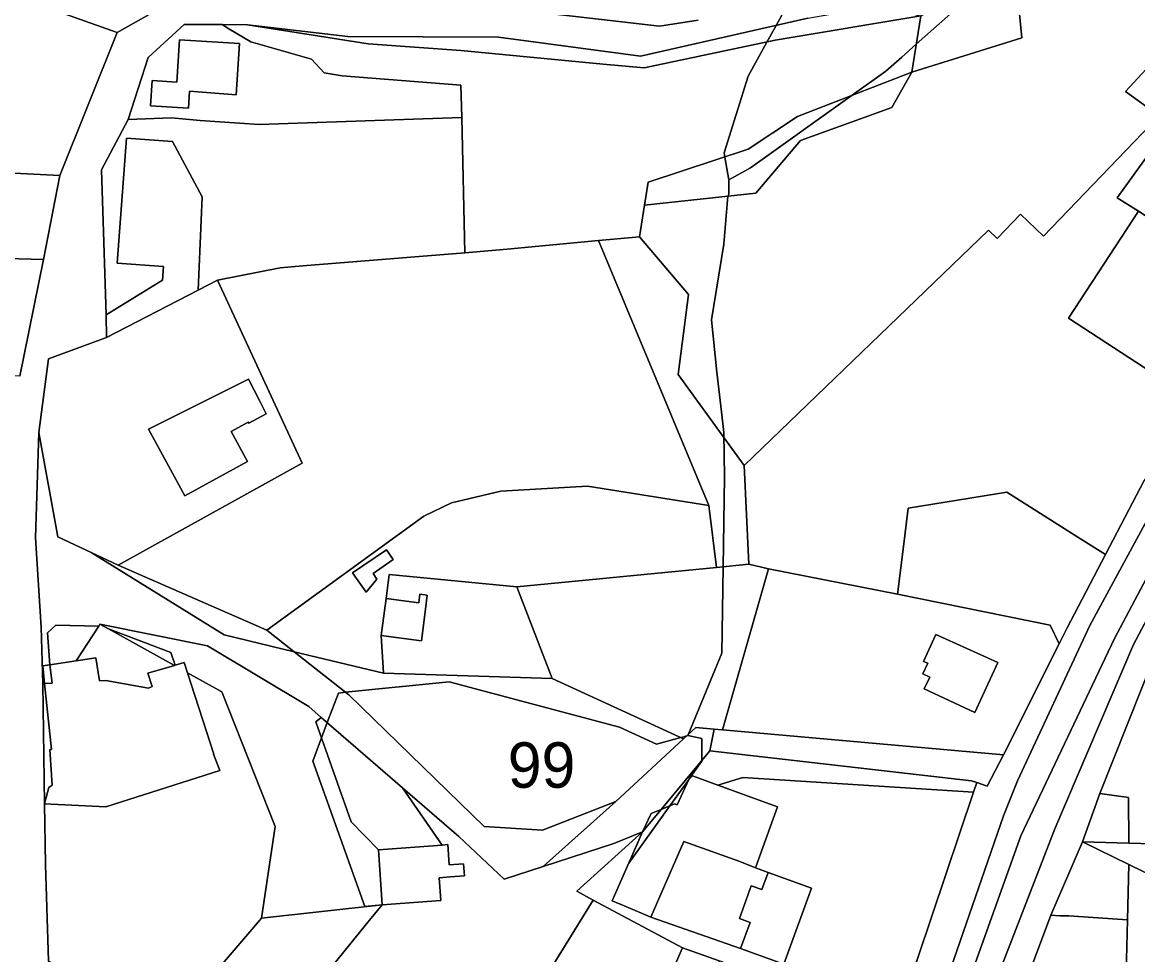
# Model space of a CAD drawing. Extents: x -502026 to -497664, y -1143484 to -1138019.
# Drawn here: x -498249.6 to -498053.3, y -1140095.6 to -1139931.4 of the extents above; entities that cross this region are included whole.
import ezdxf

# ---------------------------------------------------------------- set-up
doc = ezdxf.new("R2010")
doc.units = 0
for name, color, linetype in [('25', 7, 'Continuous'), ('31', 7, 'Continuous'), ('37', 7, 'Continuous'), ('49', 7, 'Continuous'), ('55', 7, 'Continuous'), ('62', 7, 'Continuous'), ('7', 7, 'Continuous')]:
    doc.layers.add(name, color=color, linetype=linetype)

msp = doc.modelspace()

# ---------------------------------------------------------------- linework, layer by layer
at = {"layer": '25'}
for points in [[(-498232.94, -1139933.15), (-498243, -1139958.38), (-498284.72, -1139956.22), (-498294.84, -1139955.69), (-498271.76, -1139932.13), (-498277.06, -1139927.13), (-498281.47, -1139922.96), (-498283.61, -1139920.94), (-498270.97, -1139913.76), (-498253.45, -1139925.83)], [(-498005.22, -1139919.56), (-498013.29, -1139944.08), (-498013.7, -1139945.33), (-498022.56, -1139967.15), (-498037.76, -1139956.26), (-498047.52, -1139949.27), (-498049.52, -1139947.83), (-498055.44, -1139943.59), (-498027.12, -1139912.89)], [(-498093.06, -1139940.14), (-498113.16, -1139947.96), (-498121.83, -1139953.73), (-498139.45, -1139959.55), (-498140.08, -1139963.56), (-498140.96, -1139969.15), (-498148.2, -1139969.82), (-498164.29, -1139971.31), (-498171.75, -1139971.96), (-498172.29, -1139948.12), (-498172.42, -1139942.47), (-498193.31, -1139940.83), (-498196.52, -1139940.26), (-498198.73, -1139937.88), (-498209.39, -1139934.8), (-498213.26, -1139932.52), (-498214.48, -1139931.78), (-498209.97, -1139931.8), (-498188.75, -1139935.17), (-498172.43, -1139936.37), (-498147.36, -1139938.76), (-498140.19, -1139939.42), (-498117.09, -1139934.55), (-498091.45, -1139930.24)], [(-498214.48, -1139931.78), (-498213.26, -1139932.52), (-498209.39, -1139934.8), (-498198.73, -1139937.88), (-498196.52, -1139940.26), (-498193.31, -1139940.83), (-498172.42, -1139942.47), (-498172.29, -1139948.12), (-498207.94, -1139949.35), (-498218.35, -1139948.67), (-498223.36, -1139948.18), (-498230.99, -1139948.51), (-498227.48, -1139937.56), (-498221.15, -1139931.74)], [(-498211.43, -1139935.09), (-498221.96, -1139934.44), (-498222.42, -1139941.91), (-498226.78, -1139941.61), (-498227.07, -1139946.11), (-498220.39, -1139946.52), (-498220.2, -1139943.51), (-498211.98, -1139944.15)], [(-498171.75, -1139971.96), (-498200.23, -1139974.26), (-498204.27, -1139974.59), (-498215.25, -1139976.79), (-498218.65, -1139978.55), (-498217.95, -1139962.1), (-498223.18, -1139952.37), (-498231.27, -1139951.77), (-498232.95, -1139973.77), (-498224.77, -1139974.36), (-498224.96, -1139976.78), (-498234.9, -1139982.88), (-498235.68, -1139957.35), (-498230.99, -1139948.51), (-498223.36, -1139948.18), (-498218.35, -1139948.67), (-498207.94, -1139949.35), (-498172.29, -1139948.12)], [(-498047.52, -1139949.27), (-498056.92, -1139962.31), (-498053.17, -1139964.63), (-498065.44, -1139983.49), (-498043.03, -1139998.07), (-498052.15, -1140012.08), (-498058.96, -1140025.11), (-498063.8, -1140022.04), (-498076.32, -1140014.11), (-498093.67, -1140016.92), (-498094.53, -1140023.68), (-498095.59, -1140032.09), (-498118.27, -1140027.6), (-498121.71, -1140026.79), (-498122.55, -1140009.45), (-498079.55, -1139968), (-498078.04, -1139969.45), (-498073.93, -1139965.16), (-498069.88, -1139969.05), (-498049.52, -1139947.83)], [(-498037.76, -1139956.26), (-498038.47, -1139957.24), (-498039.95, -1139959.31), (-498046.76, -1139968.79), (-498053.17, -1139964.63), (-498056.92, -1139962.31), (-498047.52, -1139949.27)], [(-498243, -1139958.38), (-498245.93, -1139973.13), (-498261.03, -1139972.75), (-498285.83, -1139972.19), (-498285.53, -1139967.92), (-498284.84, -1139957.94), (-498284.72, -1139956.22)], [(-498046.76, -1139968.79), (-498030.37, -1139979.5), (-498043.03, -1139998.07), (-498065.44, -1139983.49), (-498053.17, -1139964.63)], [(-498122.55, -1140009.45), (-498121.71, -1140026.79), (-498127.44, -1140027.42), (-498128.78, -1140016.46), (-498148.2, -1139969.82), (-498140.96, -1139969.15), (-498132.36, -1139979.34), (-498134.19, -1139993.42)], [(-498245.93, -1139973.13), (-498250.05, -1139993.72), (-498260.48, -1139993.31), (-498261.03, -1139972.75)], [(-498128.78, -1140016.46), (-498127.44, -1140027.42), (-498162.57, -1140030.81), (-498185.03, -1140028.65), (-498185.61, -1140032.83), (-498186.46, -1140039.38), (-498186.06, -1140046.03), (-498201.77, -1140042.24), (-498206.6, -1140038.42), (-498178.95, -1140018.37), (-498174.11, -1140016.01), (-498165.37, -1140013.97), (-498150.14, -1140013.08)], [(-498038.09, -1140076.42), (-498054.83, -1140075.94), (-498054.88, -1140067.92), (-498059.95, -1140067.22), (-498050.2, -1140042.69), (-498038.13, -1140020.23), (-498028.18, -1140017.21), (-498036.75, -1140034.66)], [(-498187.23, -1140029.44), (-498187.89, -1140028.43), (-498184.33, -1140025.98), (-498185.54, -1140024.27), (-498191.48, -1140028.34), (-498189.13, -1140031.76)], [(-498095.59, -1140032.09), (-498068.7, -1140037.55), (-498067.12, -1140040.83), (-498076.93, -1140060.36), (-498126.38, -1140056.01), (-498118.27, -1140027.6)], [(-498162.57, -1140030.81), (-498156.37, -1140046.94), (-498186.06, -1140046.03), (-498186.46, -1140039.38), (-498179.38, -1140040.3), (-498178.66, -1140034.75), (-498178.34, -1140032.27), (-498179.63, -1140032.1), (-498179.82, -1140033.59), (-498185.61, -1140032.83), (-498185.03, -1140028.65)], [(-498234.44, -1140038.19), (-498222.86, -1140044.65), (-498227.51, -1140046.01), (-498226.77, -1140048.36), (-498227.44, -1140048.62), (-498234.96, -1140047.28), (-498236.03, -1140047.34), (-498236.68, -1140043.3), (-498240.17, -1140043.84), (-498236.19, -1140037.7), (-498235.96, -1140037.35)], [(-498077.89, -1140044.15), (-498088.83, -1140039.19), (-498090.98, -1140043.93), (-498090.25, -1140044.27), (-498091.11, -1140046.12), (-498089.89, -1140046.69), (-498090.86, -1140048.78), (-498081.97, -1140052.91)], [(-498207.5, -1140089.14), (-498219.6, -1140103.27), (-498225.05, -1140106.86), (-498243.76, -1140097.36), (-498245.01, -1140096.73), (-498245.56, -1140079.69), (-498245.72, -1140069), (-498234.92, -1140069.54), (-498214.88, -1140063.12), (-498216, -1140060.27), (-498215.9, -1140060.24), (-498220.57, -1140045.92), (-498214.54, -1140049.28), (-498205.11, -1140073.02)], [(-498082.17, -1140066.94), (-498096.88, -1140110.66), (-498097.6, -1140107.01), (-498126.96, -1140096.68), (-498133.43, -1140094.4), (-498149.15, -1140085.96), (-498152.03, -1140084.42), (-498140.47, -1140073.95), (-498145.78, -1140086.1), (-498143.39, -1140087.11), (-498138.98, -1140088.97), (-498123.21, -1140094.49), (-498115.58, -1140097.28), (-498110.72, -1140083.87), (-498118.34, -1140081.1), (-498120.54, -1140080.27), (-498116.68, -1140069.57), (-498127.17, -1140065.71), (-498122.79, -1140064.35)], [(-498133.43, -1140094.4), (-498141.65, -1140113.1), (-498149.73, -1140131.47), (-498171.57, -1140122.26), (-498149.15, -1140085.96)], [(-498126.96, -1140096.68), (-498134.08, -1140116.1), (-498141.65, -1140113.1), (-498133.43, -1140094.4)]]:
    msp.add_lwpolyline(points, close=True, dxfattribs=at)
msp.add_lwpolyline([(-498219.6, -1140103.27), (-498207.5, -1140089.14), (-498186.28, -1140086.78), (-498175.94, -1140086.02), (-498176.23, -1140082.04), (-498174.32, -1140081.9), (-498171.8, -1140081.71), (-498171.95, -1140079.59), (-498174.47, -1140079.78), (-498174.73, -1140076.2), (-498175.71, -1140076.27), (-498182.72, -1140066.17), (-498172.81, -1140074.74), (-498164.8, -1140082.31), (-498157.95, -1140080.06), (-498145.53, -1140075.99), (-498140.47, -1140073.95), (-498152.03, -1140084.42), (-498149.15, -1140085.96), (-498171.57, -1140122.26)], dxfattribs=at)
at = {"layer": '31'}
for points in [[(-498128.78, -1140016.46), (-498150.14, -1140013.08), (-498165.37, -1140013.97), (-498174.11, -1140016.01), (-498178.95, -1140018.37), (-498206.6, -1140038.42), (-498232.76, -1140027.01), (-498200.34, -1140009.02), (-498215.25, -1139976.79), (-498204.27, -1139974.59), (-498200.23, -1139974.26), (-498171.75, -1139971.96), (-498164.29, -1139971.31), (-498148.2, -1139969.82)], [(-498232.76, -1140027.01), (-498237.54, -1140024.75), (-498243.41, -1140021.97), (-498246.71, -1140003.61), (-498245.04, -1139990.65), (-498234.8, -1139986.89), (-498218.65, -1139978.55), (-498215.25, -1139976.79), (-498200.34, -1140009.02)], [(-498206.71, -1140000.31), (-498207.85, -1139998.08), (-498209.83, -1139994.23), (-498227.44, -1140003.04), (-498223.9, -1140009.5), (-498221.02, -1140014.76), (-498209.97, -1140008.71), (-498212.85, -1140003.44), (-498209.87, -1140001.81), (-498209.77, -1140001.99)]]:
    msp.add_lwpolyline(points, close=True, dxfattribs=at)
at = {"layer": '37'}
for points in [[(-498027.12, -1139912.89), (-498055.44, -1139943.59), (-498049.52, -1139947.83), (-498069.88, -1139969.05), (-498073.93, -1139965.16), (-498078.04, -1139969.45), (-498079.55, -1139968), (-498122.55, -1140009.45), (-498134.19, -1139993.42), (-498132.36, -1139979.34), (-498140.96, -1139969.15), (-498140.08, -1139963.56), (-498120.51, -1139961.49), (-498112.66, -1139952.19), (-498096.58, -1139946.36), (-498093.06, -1139940.14), (-498073.7, -1139934.12), (-498075.01, -1139920.31), (-498049.57, -1139915.41), (-498034.71, -1139902.25)], [(-498140.08, -1139963.56), (-498139.45, -1139959.55), (-498121.83, -1139953.73), (-498113.16, -1139947.96), (-498093.06, -1139940.14), (-498096.58, -1139946.36), (-498112.66, -1139952.19), (-498120.51, -1139961.49)]]:
    msp.add_lwpolyline(points, close=True, dxfattribs=at)
at = {"layer": '49'}
for points in [[(-498250.38, -1140311.13), (-498234.18, -1140304.59), (-498200.76, -1140288.41), (-498185, -1140278.13), (-498165.27, -1140261.46), (-498146.68, -1140243.08), (-498132.7, -1140222.36), (-498124.12, -1140203.18), (-498087.57, -1140113.05), (-498073.83, -1140074.63), (-498057.39, -1140039.9), (-498045.16, -1140016.86)], [(-498041.93, -1140018.22), (-498054.05, -1140040.95), (-498067.9, -1140073.44), (-498081.58, -1140108.86), (-498119.83, -1140203.03), (-498130.05, -1140224.19), (-498140.17, -1140240.38), (-498158.83, -1140262.89), (-498179.66, -1140279.76), (-498194.41, -1140288.79), (-498230.08, -1140306.72), (-498248.48, -1140314.49), (-498266.76, -1140316.28)]]:
    msp.add_lwpolyline(points, dxfattribs=at)
at = {"layer": '55'}
for points in [[(-498222.1, -1139927.02), (-498232.94, -1139933.15), (-498253.45, -1139925.83)], [(-498250.05, -1139993.72), (-498245.93, -1139973.13), (-498243, -1139958.38), (-498232.94, -1139933.15), (-498222.1, -1139927.02)], [(-498168.64, -1139928.5), (-498137.45, -1139932.04), (-498130.68, -1139931.01)], [(-498130.68, -1139931.01), (-498137.45, -1139932.04), (-498168.64, -1139928.5)], [(-498111.37, -1139930.64), (-498140.83, -1139937.33), (-498165.79, -1139933.98), (-498192.35, -1139933.9), (-498209.97, -1139931.8), (-498214.48, -1139931.78), (-498221.15, -1139931.74), (-498227.48, -1139937.56), (-498230.99, -1139948.51), (-498235.68, -1139957.35), (-498234.9, -1139982.88), (-498234.8, -1139986.89), (-498245.04, -1139990.65), (-498246.71, -1140003.61), (-498247.34, -1140022.19), (-498246.29, -1140037.92), (-498246.03, -1140047.86), (-498245.72, -1140069), (-498245.56, -1140079.69), (-498245.01, -1140096.73), (-498244.66, -1140107.6), (-498249.22, -1140122.8), (-498250.18, -1140130.39)], [(-498096.88, -1140110.66), (-498082.17, -1140066.94), (-498081.61, -1140065.28), (-498079.79, -1140065.92), (-498076.93, -1140060.36), (-498067.12, -1140040.83), (-498065.77, -1140038.15), (-498058.96, -1140025.11), (-498052.15, -1140012.08)], [(-498250.87, -1140307.86), (-498235.28, -1140301.81), (-498197.77, -1140282.61), (-498187.37, -1140275.36), (-498183.78, -1140272.87), (-498164.48, -1140254.47), (-498149.3, -1140237.45), (-498137.41, -1140220.42), (-498127.49, -1140201.05), (-498108.39, -1140152.98), (-498090.56, -1140110.67), (-498076.9, -1140071.11), (-498074.46, -1140064.99), (-498061.7, -1140037.59), (-498049.31, -1140014.76)], [(-498049.31, -1140014.76), (-498061.7, -1140037.59), (-498074.46, -1140064.99), (-498076.9, -1140071.11), (-498090.56, -1140110.67)], [(-498045.16, -1140016.86), (-498057.39, -1140039.9), (-498073.83, -1140074.63), (-498087.57, -1140113.05), (-498124.12, -1140203.18), (-498132.7, -1140222.36), (-498146.68, -1140243.08), (-498165.27, -1140261.46), (-498185, -1140278.13), (-498200.76, -1140288.41), (-498234.18, -1140304.59), (-498250.38, -1140311.13)], [(-498266.76, -1140316.28), (-498248.48, -1140314.49), (-498230.08, -1140306.72), (-498194.41, -1140288.79), (-498179.66, -1140279.76), (-498158.83, -1140262.89), (-498140.17, -1140240.38), (-498130.05, -1140224.19), (-498119.83, -1140203.03), (-498081.58, -1140108.86), (-498067.9, -1140073.44), (-498054.05, -1140040.95), (-498041.93, -1140018.22)], [(-498050.2, -1140042.69), (-498059.95, -1140067.22), (-498062.98, -1140075.71), (-498068.59, -1140088.62), (-498078.48, -1140115.11), (-498086.46, -1140136.48), (-498094.6, -1140155.29), (-498100.22, -1140169.17), (-498105.78, -1140183.21), (-498111.53, -1140197.11), (-498117.56, -1140210.67), (-498124.37, -1140224.17), (-498132.85, -1140238.27), (-498138.3, -1140246.91), (-498142.87, -1140252.35), (-498145.2, -1140254.17), (-498154, -1140264.6), (-498169.24, -1140276.07), (-498177.05, -1140282.16), (-498192.83, -1140291.71), (-498235.15, -1140314.06), (-498240.77, -1140315.36), (-498247.78, -1140316.98), (-498250.06, -1140318.42)], [(-498044.98, -1140084.53), (-498054.82, -1140079.71), (-498062.98, -1140075.71), (-498054.83, -1140075.94), (-498038.09, -1140076.42)], [(-498051.72, -1140319.34), (-498061.89, -1140318.32), (-498061.58, -1140308.6), (-498061.2, -1140296.41), (-498060.62, -1140277.91), (-498060.46, -1140272.92), (-498059.88, -1140254.43), (-498059.44, -1140240.26), (-498059, -1140226.24), (-498058.33, -1140212.15), (-498057.99, -1140198.15), (-498057.65, -1140184.15), (-498057.31, -1140170.16), (-498056.94, -1140156.38), (-498056.72, -1140150.13), (-498056.26, -1140137.11), (-498055.98, -1140125.71), (-498055.73, -1140115.3), (-498055.07, -1140089.45), (-498054.82, -1140079.71), (-498044.98, -1140084.53)]]:
    msp.add_lwpolyline(points, dxfattribs=at)
for points in [[(-498211.43, -1139935.09), (-498211.98, -1139944.15), (-498220.2, -1139943.51), (-498220.39, -1139946.52), (-498227.07, -1139946.11), (-498226.78, -1139941.61), (-498222.42, -1139941.91), (-498221.96, -1139934.44)], [(-498218.65, -1139978.55), (-498234.8, -1139986.89), (-498234.9, -1139982.88), (-498224.96, -1139976.78), (-498224.77, -1139974.36), (-498232.95, -1139973.77), (-498231.27, -1139951.77), (-498223.18, -1139952.37), (-498217.95, -1139962.1)], [(-498206.71, -1140000.31), (-498209.77, -1140001.99), (-498209.87, -1140001.81), (-498212.85, -1140003.44), (-498209.97, -1140008.71), (-498221.02, -1140014.76), (-498223.9, -1140009.5), (-498227.44, -1140003.04), (-498209.83, -1139994.23), (-498207.85, -1139998.08)], [(-498237.54, -1140024.75), (-498214.08, -1140039.27), (-498201.77, -1140042.24), (-498192.15, -1140049.84), (-498168.33, -1140073.01), (-498158.05, -1140073.65), (-498145.13, -1140068.61), (-498157.95, -1140080.06), (-498164.8, -1140082.31), (-498172.81, -1140074.74), (-498182.72, -1140066.17), (-498197.01, -1140053.8), (-498199.22, -1140051.89), (-498217.04, -1140041.19), (-498235.96, -1140037.35), (-498236.19, -1140037.7), (-498243.74, -1140037.56), (-498245.2, -1140038.91), (-498244.79, -1140044.56), (-498246.03, -1140044.69), (-498245.73, -1140047.84), (-498246.03, -1140047.86), (-498246.29, -1140037.92), (-498247.34, -1140022.19), (-498246.71, -1140003.61), (-498243.41, -1140021.97)], [(-498058.96, -1140025.11), (-498065.77, -1140038.15), (-498067.12, -1140040.83), (-498068.7, -1140037.55), (-498095.59, -1140032.09), (-498094.53, -1140023.68), (-498093.67, -1140016.92), (-498076.32, -1140014.11), (-498063.8, -1140022.04)], [(-498232.76, -1140027.01), (-498206.6, -1140038.42), (-498201.77, -1140042.24), (-498214.08, -1140039.27), (-498237.54, -1140024.75)], [(-498187.23, -1140029.44), (-498189.13, -1140031.76), (-498191.48, -1140028.34), (-498185.54, -1140024.27), (-498184.33, -1140025.98), (-498187.89, -1140028.43)], [(-498118.27, -1140027.6), (-498126.38, -1140056.01), (-498127.83, -1140055.88), (-498131.04, -1140055.59), (-498133.22, -1140057.57), (-498156.37, -1140046.94), (-498162.57, -1140030.81), (-498127.44, -1140027.42), (-498121.71, -1140026.79)], [(-498186.46, -1140039.38), (-498185.61, -1140032.83), (-498179.82, -1140033.59), (-498179.63, -1140032.1), (-498178.34, -1140032.27), (-498178.66, -1140034.75), (-498179.38, -1140040.3)], [(-498197.01, -1140053.8), (-498197.94, -1140054.56), (-498191.73, -1140072.2), (-498186.94, -1140077.09), (-498186.28, -1140086.78), (-498207.5, -1140089.14), (-498205.11, -1140073.02), (-498214.54, -1140049.28), (-498220.57, -1140045.92), (-498221.16, -1140044.12), (-498222.73, -1140044.61), (-498223.5, -1140042.38), (-498234.44, -1140038.19), (-498235.96, -1140037.35), (-498217.04, -1140041.19), (-498199.22, -1140051.89)], [(-498236.19, -1140037.7), (-498240.17, -1140043.84), (-498244.79, -1140044.56), (-498245.2, -1140038.91), (-498243.74, -1140037.56)], [(-498222.73, -1140044.61), (-498222.86, -1140044.65), (-498234.44, -1140038.19), (-498223.5, -1140042.38)], [(-498077.89, -1140044.15), (-498081.97, -1140052.91), (-498090.86, -1140048.78), (-498089.89, -1140046.69), (-498091.11, -1140046.12), (-498090.25, -1140044.27), (-498090.98, -1140043.93), (-498088.83, -1140039.19)], [(-498222.86, -1140044.65), (-498222.73, -1140044.61), (-498221.16, -1140044.12), (-498220.57, -1140045.92), (-498215.9, -1140060.24), (-498216, -1140060.27), (-498214.88, -1140063.12), (-498234.92, -1140069.54), (-498245.72, -1140069), (-498244.98, -1140066.11), (-498244.39, -1140065.72), (-498244.78, -1140059.46), (-498244.52, -1140059.44), (-498245.73, -1140047.84), (-498244.36, -1140047.77), (-498244.79, -1140044.56), (-498240.17, -1140043.84), (-498236.68, -1140043.3), (-498236.03, -1140047.34), (-498234.96, -1140047.28), (-498227.44, -1140048.62), (-498226.77, -1140048.36), (-498227.51, -1140046.01)], [(-498186.06, -1140046.03), (-498156.37, -1140046.94), (-498133.22, -1140057.57), (-498145.13, -1140068.61), (-498158.05, -1140073.65), (-498168.33, -1140073.01), (-498192.15, -1140049.84), (-498201.77, -1140042.24)], [(-498245.73, -1140047.84), (-498246.03, -1140044.69), (-498244.79, -1140044.56), (-498244.36, -1140047.77)], [(-498245.72, -1140069), (-498246.03, -1140047.86), (-498245.73, -1140047.84), (-498244.52, -1140059.44), (-498244.78, -1140059.46), (-498244.39, -1140065.72), (-498244.98, -1140066.11)], [(-498182.72, -1140066.17), (-498175.71, -1140076.27), (-498186.94, -1140077.09), (-498191.73, -1140072.2), (-498197.94, -1140054.56), (-498197.01, -1140053.8)], [(-498127.83, -1140055.88), (-498128.63, -1140059.66), (-498137.2, -1140070.01), (-498138.96, -1140070.73), (-498140.47, -1140073.95), (-498145.53, -1140075.99), (-498157.95, -1140080.06), (-498145.13, -1140068.61), (-498133.22, -1140057.57), (-498131.04, -1140055.59)], [(-498126.38, -1140056.01), (-498076.93, -1140060.36), (-498079.79, -1140065.92), (-498081.61, -1140065.28), (-498082.53, -1140064.96), (-498128.63, -1140059.66), (-498127.83, -1140055.88)], [(-498081.61, -1140065.28), (-498082.17, -1140066.94), (-498122.79, -1140064.35), (-498127.17, -1140065.71), (-498131.65, -1140064.06), (-498132.33, -1140064.71), (-498134.37, -1140069.22), (-498134.83, -1140069.03), (-498137.2, -1140070.01), (-498128.63, -1140059.66), (-498082.53, -1140064.96)], [(-498127.17, -1140065.71), (-498116.68, -1140069.57), (-498120.54, -1140080.27), (-498123.32, -1140079.2), (-498133.18, -1140075.63), (-498138.98, -1140088.97), (-498143.39, -1140087.11), (-498145.78, -1140086.1), (-498140.47, -1140073.95), (-498137.2, -1140070.01), (-498134.83, -1140069.03), (-498134.37, -1140069.22), (-498132.33, -1140064.71), (-498131.65, -1140064.06)], [(-498054.83, -1140075.94), (-498062.98, -1140075.71), (-498059.95, -1140067.22), (-498054.88, -1140067.92)], [(-498140.47, -1140073.95), (-498138.96, -1140070.73), (-498137.2, -1140070.01)], [(-498186.28, -1140086.78), (-498186.94, -1140077.09), (-498175.71, -1140076.27), (-498174.73, -1140076.2), (-498174.47, -1140079.78), (-498171.95, -1140079.59), (-498171.8, -1140081.71), (-498174.32, -1140081.9), (-498176.23, -1140082.04), (-498175.94, -1140086.02)], [(-498120.54, -1140080.27), (-498118.34, -1140081.1), (-498119.43, -1140084.11), (-498121.3, -1140083.43), (-498123.4, -1140089.21), (-498121.53, -1140089.89), (-498123.21, -1140094.49), (-498138.98, -1140088.97), (-498133.18, -1140075.63), (-498123.32, -1140079.2)], [(-498054.82, -1140079.71), (-498055.07, -1140089.45), (-498056.85, -1140089.33), (-498065.42, -1140088.76), (-498066.98, -1140088.72), (-498068.59, -1140088.62), (-498062.98, -1140075.71)], [(-498123.21, -1140094.49), (-498121.53, -1140089.89), (-498123.4, -1140089.21), (-498121.3, -1140083.43), (-498119.43, -1140084.11), (-498118.34, -1140081.1), (-498110.72, -1140083.87), (-498115.58, -1140097.28)], [(-498055.07, -1140089.45), (-498055.73, -1140115.3), (-498078.48, -1140115.11), (-498068.59, -1140088.62), (-498066.98, -1140088.72), (-498065.42, -1140088.76), (-498056.85, -1140089.33)]]:
    msp.add_lwpolyline(points, close=True, dxfattribs=at)
at = {"layer": '62'}
for points in [[(-498205.62, -1140110.59), (-498188.5, -1140089.5), (-498186.28, -1140086.78), (-498175.94, -1140086.02), (-498176.23, -1140082.04), (-498174.32, -1140081.9), (-498171.8, -1140081.71), (-498171.95, -1140079.59), (-498174.47, -1140079.78), (-498174.73, -1140076.2), (-498175.71, -1140076.27), (-498182.72, -1140066.17), (-498172.81, -1140074.74), (-498164.8, -1140082.31), (-498157.95, -1140080.06), (-498145.53, -1140075.99), (-498140.47, -1140073.95), (-498142.88, -1140079.46), (-498135.64, -1140069.36), (-498132.38, -1140064.82), (-498132.24, -1140064.62), (-498130, -1140061.5), (-498130, -1140061.31), (-498130, -1140057.5), (-498132.5, -1140057), (-498132.44, -1140056.86), (-498126.5, -1140042.5), (-498126.25, -1140027.29), (-498126, -1140011.5), (-498126.12, -1140003.61), (-498126.55, -1140000), (-498127.39, -1139992.97), (-498128.34, -1139983.76), (-498126.12, -1139970.43), (-498125.46, -1139962.01), (-498125.25, -1139961.62), (-498125.25, -1139959.12), (-498121.44, -1139957), (-498103.52, -1139944.21), (-498097.62, -1139940), (-498094.83, -1139937.51), (-498092.26, -1139935.22), (-498076.55, -1139921.24)], [(-498076.55, -1139921.24), (-498092.26, -1139935.22), (-498094.83, -1139937.51), (-498097.62, -1139940), (-498103.52, -1139944.21), (-498121.44, -1139957), (-498125.25, -1139959.12), (-498125.97, -1139955.1), (-498126.03, -1139954.74), (-498126.09, -1139954.37), (-498121.84, -1139940.87), (-498118.56, -1139934.86), (-498116.95, -1139931.91), (-498114.96, -1139928.27)], [(-498114.96, -1139928.27), (-498116.95, -1139931.91), (-498118.56, -1139934.86), (-498121.84, -1139940.87), (-498126.09, -1139954.37), (-498126.03, -1139954.74), (-498125.97, -1139955.1), (-498125.25, -1139959.12), (-498125.25, -1139961.62), (-498125.46, -1139962.01), (-498126.12, -1139970.43), (-498128.34, -1139983.76), (-498127.39, -1139992.97), (-498126.55, -1140000), (-498126.12, -1140003.61), (-498126, -1140011.5), (-498126.25, -1140027.29), (-498126.5, -1140042.5), (-498132.44, -1140056.86), (-498132.5, -1140057), (-498132.63, -1140057.04), (-498133.19, -1140057.19), (-498133.73, -1140057.33), (-498138, -1140058.5), (-498144.5, -1140055.5), (-498174.5, -1140047.5), (-498192.74, -1140049.37), (-498194, -1140049.5), (-498195.95, -1140054.71), (-498196.95, -1140057.37), (-498198.5, -1140061.5), (-498189.35, -1140087.12), (-498186.28, -1140086.78), (-498188.5, -1140089.5), (-498205.62, -1140110.59)]]:
    msp.add_lwpolyline(points, dxfattribs=at)
msp.add_lwpolyline([(-498132.5, -1140057), (-498130, -1140057.5), (-498130, -1140061.31), (-498130, -1140061.5), (-498132.24, -1140064.62), (-498132.38, -1140064.82), (-498135.64, -1140069.36), (-498142.88, -1140079.46), (-498140.47, -1140073.95), (-498145.53, -1140075.99), (-498157.95, -1140080.06), (-498164.8, -1140082.31), (-498172.81, -1140074.74), (-498182.72, -1140066.17), (-498175.71, -1140076.27), (-498174.73, -1140076.2), (-498174.47, -1140079.78), (-498171.95, -1140079.59), (-498171.8, -1140081.71), (-498174.32, -1140081.9), (-498176.23, -1140082.04), (-498175.94, -1140086.02), (-498186.28, -1140086.78), (-498189.35, -1140087.12), (-498198.5, -1140061.5), (-498196.95, -1140057.37), (-498195.95, -1140054.71), (-498194, -1140049.5), (-498192.74, -1140049.37), (-498174.5, -1140047.5), (-498144.5, -1140055.5), (-498138, -1140058.5), (-498133.73, -1140057.33), (-498133.19, -1140057.19), (-498132.63, -1140057.04)], close=True, dxfattribs=at)
at = {"layer": '7'}
for points in [[(-498093.06, -1139940.14), (-498091.45, -1139930.24), (-498075.01, -1139920.31), (-498073.7, -1139934.12)], [(-498091.45, -1139930.24), (-498117.09, -1139934.55), (-498140.19, -1139939.42), (-498147.36, -1139938.76), (-498172.43, -1139936.37), (-498188.75, -1139935.17), (-498209.97, -1139931.8), (-498192.35, -1139933.9), (-498165.79, -1139933.98), (-498140.83, -1139937.33), (-498111.37, -1139930.64), (-498099.21, -1139928.56)]]:
    msp.add_lwpolyline(points, close=True, dxfattribs=at)

# ---------------------------------------------------------------- texts
at = {"layer": '62'}
msp.add_text('99', height=8, dxfattribs=at).set_placement((-498164.18, -1140066.18))

doc.saveas('drawing.dxf')
